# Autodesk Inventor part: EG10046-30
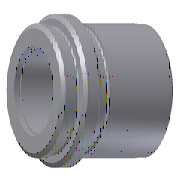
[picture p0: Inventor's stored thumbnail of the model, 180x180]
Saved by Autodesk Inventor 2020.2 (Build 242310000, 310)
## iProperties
Manager: www.cadconsulting.pl
Company: Fabian Stasiak CAD Consulting
Created: 2014-02
Part Number: EG10046-30
Material: DIN 1.7131
Description: Leader Pin Bushings
Document SubType Name: Modeling
Designer: F.Stasiak
Standard Revision: 1
Manufacturer: DME
Language: pl-PL
Size Designation: 46-30
Categories: <MemberInstance><Categories><Category DisplayName="Forma wtryskowa" InternalName="349578f2-f4d4-4954-8c09-8e99297a61c0" Mnemonic="MOLD"><Category DisplayName="K
Density: 7.85 g/cm^3
Appearance: Domyślna
Catalog Web Link: www.expertbooks.pl
IsCustomPart: 0
Author: F.Stasiak
Subject: Zbiór ćwiczeń. Autodesk Inventor 2020. Kurs Professional
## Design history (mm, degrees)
sketch "Sketch1"
  geometry: L1 (0, -16.8)-(0, 9.8) reference; L2 (0, 15)-(21, 15); L3 (21, 15)-(21, 7); L4 (21, 7)-(20.5, 7); L5 (20.5, 7)-(20.5, 6); L6 (20.5, 6)-(23.5, 6); L7 (23.5, 6)-(23.5, 0); L8 (23.5, 0)-(20.5, 0); L9 (20.5, 0)-(20.5, -1); L10 (20.5, -1)-(21, -1); L11 (21, -1)-(21, -39); L12 (21, -39)-(20.95, -39); L13 (20.95, -39)-(20.95, -40); L14 (20.95, -40)-(0, -40); L15 (0, 15)-(0, -40); 1 further point
  constraints: 28 end point, 7 parallel, 5 perpendicular, 2 collinear, 2 equal length, 2 point on line, 1 horizontal alignment
  dimensions: "d0" = 42 diameter of L11 L1 (= D); "d2" = 1 distance between parallel lines of L14 L12; "d27" = 41.9 diameter of L13 L1 (= D_Guide); "d4" = 47 diameter of L7 L1 (= D2); "d5" = 42 diameter of L3 L1 (= D1); "d6" = 6 distance between parallel lines of L8 L6 (= H_); "d7" = 46 distance between parallel lines of L14 L6 (= L); "d8" = 9 distance between parallel lines of L6 L2 (= L1); "d9" = 1 distance between parallel lines of L10 L8; "d10" = 0.5 distance between parallel lines of L11 L9
revolve "Revolution1" sketch "Sketch1" stored, may be unused: angle "d11" = 90 deg
sketch "Sketch2"
  geometry: L1 (-20.95, -40)-(20.95, -40) reference; L2 (15, -40)-(15, 6); L3 (15, 6)-(15, 6); L4 (15, 6)-(15, 61); L5 (0, -40)-(0, 61); L6 (0, 61)-(15, 61); L7 (15, -40)-(0, -40)
  constraints: 12 end point, 3 perpendicular, 2 collinear, 1 midpoint, 1 parallel, 1 point on line
  dimensions: "d12" = 30 diameter of L2 L5 (= d_); "d13" = 46 distance of L2.start L2.end (= l_); "d14" = 55 distance of L3.end L4.end (= L + L1); "d15" = 30 diameter of L4 L5 (= d3)
revolve "Revolution2" sketch "Sketch2" stored, may be unused: angle "d16" = 90 deg
chamfer "Chamfer1" distance "d17" = 0.5; stored, may be unused: second distance "d18" = 2, angle "d19" = 45 deg
fillet "Fillet1" dims "d20" = 0.3
fillet "Fillet2" dims "d21" = 0.8
body "Solid1"
other parameters: "d_" = 30 [user parameter; used in 1 equation term], "L" = 46 [user parameter; used in 2 equation terms], "D" = 42 [user parameter; used in 1 equation term], "D1" = 42 [user parameter; used in 1 equation term], "D2" = 47 [user parameter; used in 1 equation term], "H_" = 6 [user parameter; used in 1 equation term], "L1" = 9 [user parameter; used in 2 equation terms], "l_" = 46 [user parameter; used in 1 equation term], "d3" = 30 [user parameter; used in 1 equation term], "D_Guide" = 41.9 [user parameter; used in 1 equation term], "d22" = 0, "d23" = 0, "d24" = 0, "d25" = 0, "d26" = 0
